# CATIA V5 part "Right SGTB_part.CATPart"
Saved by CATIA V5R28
Part number: Right SGTB_part
Definition: design
Nomenclature: Right SGTB_part
Source: Unknown
Bounding box of the stored display mesh (mm): x -22.35 to 22.35, y -22.35 to 22.35, z 0 to 3.582
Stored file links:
  D:\paraturbo-cad\STEP\Turbocompressor_for_Christophe\Right SGTB_part.CATPart
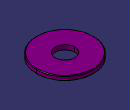
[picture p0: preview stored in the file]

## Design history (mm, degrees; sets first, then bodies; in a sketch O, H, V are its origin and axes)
Body1 "MANIFOLD_SOLID_BREP #1108" (main body)
  Solid1: solid without history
